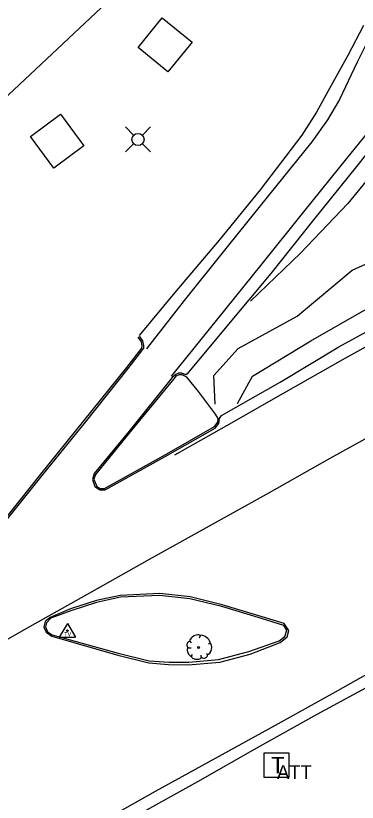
# Model space of a CAD drawing. Extents: x 1042086 to 1119166, y 1916606 to 1927565.
# Drawn here: x 1043321.6 to 1043446.1, y 1926246.9 to 1926533.5 of the extents above; entities that cross this region are included whole.
import ezdxf

# ---------------------------------------------------------------- set-up
doc = ezdxf.new("R2010")
doc.units = 0
for name, color, linetype in [('S_BUILDING', 7, 'Continuous'), ('S_CURB', 7, 'Continuous'), ('S_EDGE_CONCRETE', 7, 'Continuous'), ('S_EDGE_PAVEMENT', 7, 'Continuous'), ('S_GRAVEL_ROAD', 7, 'Continuous'), ('S_SANITARY_SEWER', 7, 'Continuous'), ('S_SECONDARY_CTL', 7, 'Continuous'), ('S_SHOULDER', 7, 'Continuous'), ('S_TELEPHONE_UTILITIES', 7, 'Continuous'), ('S_TELEPHONE_UTILITIES_ANNOT', 7, 'Continuous'), ('S_TREE', 7, 'Continuous'), ('S_UTILITY_POLE', 7, 'Continuous')]:
    doc.layers.add(name, color=color, linetype=linetype)

msp = doc.modelspace()

# ---------------------------------------------------------------- linework, layer by layer
at = {"layer": 'S_BUILDING'}
for points in [[(1043377.05, 1926513.02), (1043366.16, 1926521.85), (1043375, 1926532.74), (1043385.88, 1926523.9)], [(1043335.43, 1926477.99), (1043326.93, 1926489.42), (1043337.87, 1926497.55), (1043346.37, 1926486.13)]]:
    msp.add_lwpolyline(points, close=True, dxfattribs=at)
at = {"layer": 'S_CURB'}
for points in [[(1043366.1, 1926416.39), (1043367.26, 1926414.66), (1043367.55, 1926413.33), (1043367.41, 1926412.29), (1043361.98, 1926405.29), (1043346.23, 1926385.88), (1043330.59, 1926366.38), (1043314.91, 1926346.91), (1043304.94, 1926334.4), (1043303.88, 1926333.32), (1043301.33, 1926332.15), (1043298.81, 1926332.56), (1043296.65, 1926334.61), (1043295.87, 1926337.66), (1043296.75, 1926340.95), (1043297.22, 1926342.73), (1043296.76, 1926342.83)], [(1043379.95, 1926402.2), (1043379.15, 1926401.22), (1043363.27, 1926381.9), (1043350.6, 1926366.31), (1043350.01, 1926364.57), (1043351.13, 1926361.96), (1043352.32, 1926361.27), (1043353.92, 1926361.17)], [(1043395.4, 1926386.78), (1043394.39, 1926388.35), (1043388.16, 1926396.54), (1043383.95, 1926401.75), (1043383.47, 1926402.08), (1043382.2, 1926402.64), (1043381, 1926402.63), (1043379.95, 1926402.2)], [(1043353.92, 1926361.17), (1043375.76, 1926373.34), (1043393.97, 1926383.77), (1043395.3, 1926385.42), (1043395.4, 1926386.78)]]:
    msp.add_lwpolyline(points, dxfattribs=at)
msp.add_lwpolyline([(1043332.41, 1926310.83), (1043333.21, 1926309.01), (1043334.89, 1926307.95), (1043358.95, 1926301.16), (1043370.26, 1926298.38), (1043377.48, 1926297.92), (1043384.68, 1926297.93), (1043395.53, 1926298.88), (1043406.54, 1926301.87), (1043417.57, 1926305.75), (1043419.6, 1926307.23), (1043420.37, 1926309.61), (1043419.24, 1926311.3), (1043411.16, 1926313.8), (1043396.64, 1926318.17), (1043385.04, 1926320.99), (1043374.01, 1926322.28), (1043359.72, 1926321.6), (1043351.03, 1926319.72), (1043341.62, 1926316.68), (1043334.4, 1926313.99), (1043332.79, 1926312.32)], close=True, dxfattribs=at)
at = {"layer": 'S_EDGE_CONCRETE'}
msp.add_lwpolyline([(1043331.81, 1926310.64), (1043332.7, 1926308.84), (1043334.74, 1926307.42), (1043358.77, 1926300.54), (1043370.05, 1926297.65), (1043377.23, 1926297.06), (1043384.42, 1926296.99), (1043395.99, 1926297.91), (1043407.01, 1926300.88), (1043417.91, 1926305.04), (1043420.49, 1926307.11), (1043421.13, 1926309.51), (1043419.44, 1926312.07), (1043411.34, 1926314.51), (1043396.82, 1926318.86), (1043385.16, 1926321.72), (1043374.13, 1926322.98), (1043359.65, 1926322.23), (1043350.96, 1926320.42), (1043341.54, 1926317.38), (1043334.09, 1926314.27), (1043332.3, 1926312.76)], close=True, dxfattribs=at)
msp.add_lwpolyline([(1043062.59, 1926163.39), (1043070.11, 1926162.59), (1043076.35, 1926160.83), (1043100.56, 1926154.41), (1043124.63, 1926147.59), (1043148.74, 1926140.86), (1043160.51, 1926137.4), (1043166.21, 1926136.12), (1043176.34, 1926141.45), (1043198.18, 1926153.61), (1043219.97, 1926165.88), (1043241.79, 1926178.09), (1043263.67, 1926190.21), (1043285.53, 1926202.34), (1043307.43, 1926214.4), (1043329.32, 1926226.49), (1043351.07, 1926238.83), (1043372.48, 1926250.87), (1043394.36, 1926262.95), (1043416.28, 1926274.96), (1043438.14, 1926287.07), (1043459.9, 1926299.36)], dxfattribs=at)
at = {"layer": 'S_EDGE_PAVEMENT'}
for points in [[(1043451.46, 1926527.43), (1043446.04, 1926516.61), (1043439.62, 1926502.98), (1043435.2, 1926495.57), (1043429.45, 1926487.47), (1043413.73, 1926467.94), (1043398.64, 1926449.21), (1043383.02, 1926429.67), (1043370.46, 1926413.63), (1043369.23, 1926412.1)], [(1043379.57, 1926373.44), (1043398.5, 1926384.17), (1043420, 1926396.38), (1043441.71, 1926408.76), (1043463.61, 1926420.83), (1043485.65, 1926432.64), (1043507.89, 1926444.1), (1043530.61, 1926454.72), (1043555.31, 1926464.5), (1043578.92, 1926472.93), (1043602.85, 1926480.19), (1043626.98, 1926486.7), (1043651.29, 1926492.56), (1043675.75, 1926497.87), (1043700.4, 1926502.47), (1043725.97, 1926506.82), (1043750.72, 1926510.63), (1043775.56, 1926513.38), (1043800.45, 1926515.5), (1043825.35, 1926517.42)], [(1043457.88, 1926500.88), (1043442.15, 1926481.44), (1043426.42, 1926462.01), (1043410.8, 1926442.49), (1043395.14, 1926422.99), (1043380.86, 1926405.44), (1043378.25, 1926402.17)], [(1043366.61, 1926416.77), (1043367.8, 1926415.07), (1043368.17, 1926413.35), (1043368.1, 1926412.3), (1043362.43, 1926404.93), (1043346.84, 1926385.39), (1043331.05, 1926366), (1043315.37, 1926346.53), (1043305.25, 1926333.99), (1043303.73, 1926332.56), (1043301.19, 1926331.5), (1043298.69, 1926331.97), (1043296.12, 1926334.45), (1043295.32, 1926337.5), (1043296.15, 1926341.11), (1043296.56, 1926342.25)], [(1043379.92, 1926402.77), (1043378.62, 1926401.62), (1043362.95, 1926382.15), (1043350.19, 1926366.63), (1043349.52, 1926364.53), (1043350.37, 1926361.9), (1043352.18, 1926360.74), (1043354.15, 1926360.75)], [(1043354.15, 1926360.75), (1043376.03, 1926372.84), (1043394.27, 1926383.21), (1043395.57, 1926384.91)], [(1043102.91, 1926186.56), (1043122.35, 1926197.07), (1043144.15, 1926209.32), (1043166.01, 1926221.45), (1043187.73, 1926233.83), (1043209.7, 1926245.77), (1043231.46, 1926258.09), (1043253.4, 1926270.06), (1043275.25, 1926282.23), (1043297.21, 1926294.17), (1043326.74, 1926310.95), (1043348.54, 1926323.19), (1043370.32, 1926335.48), (1043392.17, 1926347.63), (1043414.02, 1926359.78), (1043436.24, 1926372.23), (1043453.57, 1926381.87)]]:
    msp.add_lwpolyline(points, dxfattribs=at)
at = {"layer": 'S_GRAVEL_ROAD'}
for points in [[(1043612.28, 1926681.42), (1043597.3, 1926661.51), (1043582.39, 1926641.43), (1043566.77, 1926621.92), (1043550.76, 1926602.67), (1043535.33, 1926583.01), (1043519.62, 1926563.56), (1043504.13, 1926543.91), (1043489.64, 1926523.54), (1043473.9, 1926504.06), (1043458.49, 1926484.45), (1043442.61, 1926465.11), (1043425.33, 1926446.94), (1043407.16, 1926429.44)], [(1043394.22, 1926391.92), (1043393.76, 1926402.41), (1043402.59, 1926412.28), (1043424.18, 1926423.95), (1043444.15, 1926440.82), (1043466.96, 1926451.02), (1043490.78, 1926460.69), (1043515.04, 1926469.35), (1043539.84, 1926476.76), (1043564.17, 1926484.97), (1043588.62, 1926491.99), (1043613.5, 1926496.84), (1043638.06, 1926502.09)]]:
    msp.add_lwpolyline(points, dxfattribs=at)
at = {"layer": 'S_SANITARY_SEWER'}
msp.add_line((1043379.23, 1926561.23), (1043218.13, 1926410.22), dxfattribs=at)
at = {"layer": 'S_SECONDARY_CTL'}
for p, q in [((1043340.39, 1926312.02), (1043337.38, 1926307.07)), ((1043340.39, 1926312.02), (1043343.34, 1926307.07)), ((1043337.38, 1926307.07), (1043343.34, 1926307.07))]:
    msp.add_line(p, q, dxfattribs=at)
for radius in [0.311, 0.183, 0.103]:
    msp.add_circle((1043340.39, 1926309.41), radius, dxfattribs=at)
at = {"layer": 'S_SHOULDER'}
for points in [[(1043664.29, 1926687.95), (1043661.32, 1926690.46), (1043655.23, 1926691.96), (1043647.8, 1926693.51), (1043640.81, 1926693.93), (1043633.43, 1926694), (1043625.97, 1926691.94), (1043617.88, 1926688.42), (1043611.31, 1926682.3), (1043602.78, 1926672.87), (1043587.06, 1926653.43), (1043571.43, 1926633.91), (1043555.81, 1926614.39), (1043540.03, 1926595), (1043524.28, 1926575.59), (1043508.52, 1926556.18), (1043492.66, 1926536.86), (1043477.17, 1926517.52), (1043461.38, 1926498.14), (1043445.79, 1926478.59), (1043430.12, 1926459.11), (1043414.52, 1926439.57), (1043398.52, 1926420.35), (1043384.03, 1926402.95)], [(1043448.3, 1926529.86), (1043442.61, 1926518.96), (1043435.39, 1926505.88), (1043431.16, 1926498.33), (1043425.89, 1926489.91), (1043410.65, 1926470.05), (1043395.68, 1926451.73), (1043379.59, 1926432.59), (1043366.51, 1926417)], [(1043402.36, 1926392.24), (1043407.92, 1926402.12), (1043429.15, 1926414.97), (1043451.05, 1926427.55), (1043473.82, 1926437.97), (1043496.21, 1926449.43), (1043519.25, 1926459.61), (1043542.18, 1926470.11), (1043552.41, 1926474.93), (1043576.1, 1926483.66), (1043600.3, 1926490.55), (1043624.54, 1926496.95), (1043648.88, 1926503.43), (1043673.68, 1926508.19), (1043698.4, 1926512.07), (1043722.85, 1926517.42), (1043747.76, 1926520.78), (1043772.79, 1926523.47), (1043797.88, 1926525.4), (1043822.72, 1926527.97), (1043847.76, 1926530.12)], [(1043395.57, 1926384.91), (1043395.9, 1926386.78), (1043396.52, 1926387.84), (1043417.95, 1926399.94), (1043439.4, 1926412.79), (1043461.3, 1926424.84), (1043483.14, 1926437), (1043505.37, 1926448.49), (1043528.05, 1926459.19), (1043553.89, 1926469.75), (1043577.59, 1926477.85), (1043601.56, 1926484.96), (1043625.72, 1926491.38), (1043649.95, 1926497.52), (1043674.4, 1926502.86), (1043699.15, 1926507.09), (1043725.6, 1926511.48), (1043750.38, 1926515.02), (1043775.21, 1926517.81), (1043800.11, 1926519.87), (1043824.99, 1926522.01)], [(1043384.03, 1926402.95), (1043383.62, 1926402.59), (1043382.16, 1926403.22), (1043380.96, 1926403.24), (1043379.92, 1926402.77)], [(1043063.59, 1926160.64), (1043087.45, 1926154.94), (1043111.32, 1926147.65), (1043135.23, 1926140.3), (1043159.13, 1926133.15), (1043165.36, 1926132.35), (1043169.27, 1926133.12), (1043191.11, 1926145.48), (1043213.08, 1926157.45), (1043235.23, 1926169.04), (1043257.1, 1926181.11), (1043278.59, 1926193.91), (1043300.44, 1926206.03), (1043322.31, 1926218.15), (1043344.25, 1926230.22), (1043366.13, 1926242.27), (1043387.95, 1926254.4), (1043409.64, 1926266.81), (1043431.5, 1926278.96), (1043453.48, 1926290.94)]]:
    msp.add_lwpolyline(points, dxfattribs=at)
at = {"layer": 'S_TELEPHONE_UTILITIES'}
msp.add_lwpolyline([(1043412.09, 1926255.88), (1043412.09, 1926264.88), (1043421.09, 1926264.88), (1043421.09, 1926255.88)], close=True, dxfattribs=at)
at = {"layer": 'S_TREE'}
for p, q in [((1043388.8, 1926307.55), (1043388.41, 1926306.7)), ((1043384.34, 1926303.21), (1043385.46, 1926303.21)), ((1043385, 1926305.54), (1043385.5, 1926304.96)), ((1043392.36, 1926304.76), (1043391.7, 1926304.49)), ((1043385.5, 1926300.04), (1043385.97, 1926300.73)), ((1043389.18, 1926299.76), (1043389.11, 1926300.54)), ((1043391.59, 1926300.66), (1043391.12, 1926301.08))]:
    msp.add_line(p, q, dxfattribs=at)
msp.add_circle((1043388.24, 1926303.31), 0.341, dxfattribs=at)
for centre, major_axis, ratio, start_param, end_param in [((1043386.9, 1926306.51), (1.86, 1.08), 0.471018, 0, 3.141593), ((1043390.56, 1926306.19), (-1.81, 1.36), 0.405113, 3.141593, 6.283186), ((1043384.67, 1926304.4), (0.31, 1.03), 0.646762, 0, 3.141593), ((1043384.97, 1926301.75), (-0.61, 1.6), 0.420543, 6.283185, 9.424777), ((1043391.91, 1926302.78), (0.46, 2.04), 0.482994, 3.141593, 6.283185), ((1043390.39, 1926300.26), (1.09, 0.46), 0.711534, 3.141592, 6.283185), ((1043387.43, 1926299.96), (-1.83, 0.19), 0.529943, 0, 3.141593)]:
    msp.add_ellipse(centre, major_axis=major_axis, ratio=ratio, start_param=start_param, end_param=end_param, dxfattribs=at)
at = {"layer": 'S_UTILITY_POLE'}
for p, q in [((1043364.56, 1926489.99), (1043361.57, 1926492.98)), ((1043367.74, 1926489.99), (1043370.72, 1926492.98)), ((1043364.56, 1926486.82), (1043361.57, 1926483.83)), ((1043367.74, 1926486.82), (1043370.72, 1926483.83))]:
    msp.add_line(p, q, dxfattribs=at)
msp.add_circle((1043366.15, 1926488.41), 2.21, dxfattribs=at)

# ---------------------------------------------------------------- texts
at = {"layer": 'S_SECONDARY_CTL'}
msp.add_text('TV', height=1.5, rotation=360, dxfattribs=at).set_placement((1043339.19, 1926307.4))
at = {"layer": 'S_TELEPHONE_UTILITIES'}
msp.add_text('T', height=6, rotation=360, dxfattribs=at).set_placement((1043414.66, 1926257.38))
at = {"layer": 'S_TELEPHONE_UTILITIES_ANNOT'}
msp.add_text('ATT ', height=5, dxfattribs=at).set_placement((1043416.82, 1926255.4))

doc.saveas('drawing.dxf')
